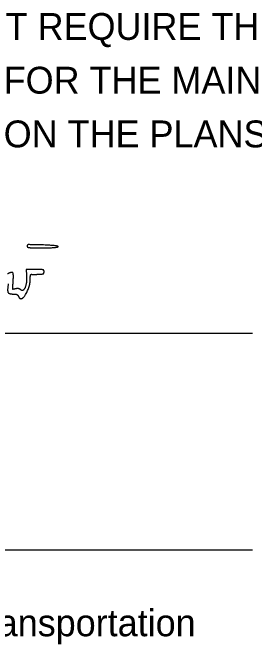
# Model space of a CAD drawing. Extents: x 0 to 36.5, y 0 to 25.3.
# Drawn here: x 26.78 to 28.038, y 7.305 to 10.597 of the extents above; entities that cross this region are included whole.
import ezdxf

# ---------------------------------------------------------------- set-up
doc = ezdxf.new("R2010")
doc.units = 0
doc.layers.add('SH_Data', color=7, linetype='Continuous')
doc.layers.add('SH_Text', color=7, linetype='Continuous')

msp = doc.modelspace()

# ---------------------------------------------------------------- linework, layer by layer
at = {"layer": 'SH_Data'}
for p, q in [((24.5279, 8.9262), (28.0279, 8.9262)), ((24.5279, 7.7968), (28.0279, 7.7968))]:
    msp.add_line(p, q, dxfattribs=at)
at = {"layer": 'SH_Text'}
msp.add_lwpolyline([(26.8966, 9.2583), (26.8497, 9.2583), (26.8519, 9.2282)], dxfattribs=at)
for points in [[(26.9304, 9.3864), (26.8636, 9.3882), (26.8555, 9.3873), (26.8555, 9.3783)], [(26.9335, 9.3708), (27.0179, 9.3714), (27.0154, 9.3841), (26.9304, 9.3864)], [(26.8555, 9.3783), (26.8555, 9.3735), (26.8865, 9.3705), (26.9335, 9.3708)], [(26.9435, 9.2463), (26.9435, 9.2556), (26.9329, 9.2583), (26.8966, 9.2583)], [(26.7823, 9.1906), (26.7857, 9.2343), (26.7766, 9.2478), (26.7525, 9.2349)], [(26.8519, 9.2282), (26.8547, 9.1882), (26.8354, 9.1411), (26.8211, 9.153)], [(26.8715, 9.205), (26.8715, 9.2211), (26.8742, 9.2339), (26.8775, 9.2334)], [(26.8775, 9.2334), (26.8808, 9.2328), (26.897, 9.2328), (26.9135, 9.2334)], [(26.9135, 9.2334), (26.9344, 9.234), (26.9435, 9.2379), (26.9435, 9.2463)], [(26.795, 9.1575), (26.7808, 9.1538), (26.7796, 9.157), (26.7823, 9.1906)], [(26.8229, 9.1063), (26.8376, 9.1063), (26.8715, 9.1751), (26.8715, 9.205)], [(26.7571, 9.1828), (26.7513, 9.1467), (26.7608, 9.1303), (26.7876, 9.1303)], [(26.8211, 9.153), (26.8153, 9.1578), (26.8036, 9.1598), (26.795, 9.1575)], [(26.7876, 9.1303), (26.7976, 9.1303), (26.8078, 9.1249), (26.8104, 9.1183)], [(26.8104, 9.1183), (26.8129, 9.1117), (26.8185, 9.1063), (26.8229, 9.1063)]]:
    msp.add_open_spline(points, degree=2, dxfattribs=at)

# ---------------------------------------------------------------- texts
at = {"layer": 'SH_Data'}
for s, p in [('IMPROVEMENT WILL NOT REQUIRE THE CLOSING TO TRAFFIC OF THE HIGHWAY', (24.5279, 10.455)), ('AND THAT PROVISIONS FOR THE MAINTENANCE AND SAFETY OF TRAFFIC', (24.5279, 10.175)), ('WILL BE AS SET FORTH ON THE PLANS AND ESTIMATES.', (24.5279, 9.895))]:
    msp.add_text(s, height=0.14, dxfattribs=at).set_placement(p)
at = {"layer": 'SH_Text'}
msp.add_text('Director, Department of Transportation', height=0.14, dxfattribs=at).set_placement((24.5279, 7.3468))

doc.saveas('drawing.dxf')
